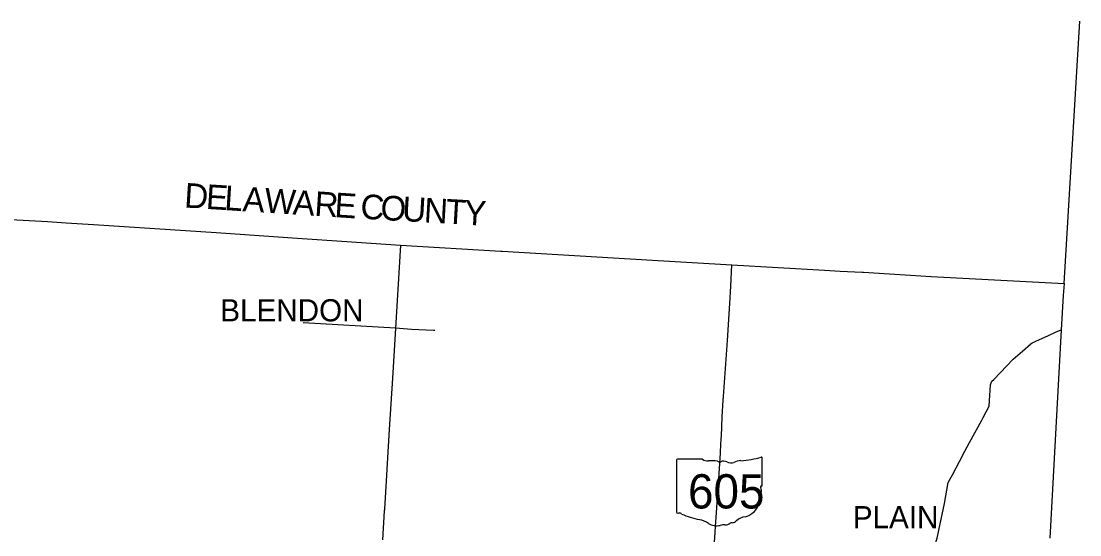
# Model space of a CAD drawing. Extents: x -1146 to -445, y -1283 to -822.
# Drawn here: x -822.8 to -715.2, y -934.9 to -882.7 of the extents above; entities that cross this region are included whole.
import ezdxf

# ---------------------------------------------------------------- set-up
doc = ezdxf.new("R2010")
doc.units = 0
for name, color, linetype in [('GM_X_Adjacent_County', 7, 'Continuous'), ('GM_X_Adjacent_County_Text', 7, 'Continuous'), ('GM_X_County', 7, 'Continuous'), ('GM_X_State_Route', 7, 'Continuous'), ('GM_X_State_Shield', 7, 'Continuous'), ('GM_X_Township', 7, 'Continuous'), ('GM_X_Township_Road', 7, 'Continuous'), ('GM_X_Township_Text', 7, 'Continuous'), ('GM_X_US_Route', 7, 'Continuous')]:
    doc.layers.add(name, color=color, linetype=linetype)

msp = doc.modelspace()

# ---------------------------------------------------------------- linework, layer by layer
at = {"layer": 'GM_X_Adjacent_County'}
msp.add_line((-716.85, -909.34), (-715.24, -882.72), dxfattribs=at)
at = {"layer": 'GM_X_County'}
msp.add_lwpolyline([(-826.99, -902.68), (-820.11, -903.07), (-818.19, -903.2), (-815.43, -903.36), (-802.96, -904.19), (-794.23, -904.79), (-790.21, -905.06), (-784.25, -905.46), (-774.05, -906.08), (-773.92, -906.08), (-758.64, -906.97), (-750.59, -907.45), (-741.19, -907.99), (-739.59, -908.09), (-737.35, -908.21), (-737.22, -908.22), (-730.34, -908.64), (-716.85, -909.34), (-716.93, -910.57), (-717.15, -914.05), (-718.3, -935.2)], dxfattribs=at)
at = {"layer": 'GM_X_State_Route'}
for points in [[(-751.65, -924.87), (-751.57, -922.88), (-751.46, -921.19), (-751.44, -920.83), (-751.04, -915.14), (-750.8, -911.37), (-750.69, -909.61), (-750.59, -907.45)], [(-751.75, -926.58), (-751.74, -926.45), (-751.66, -925.08), (-751.65, -924.87)], [(-752.28, -934.68), (-752.24, -933.98), (-752.18, -933.1), (-751.92, -929.18), (-751.85, -928.14), (-751.75, -926.58)], [(-752.34, -935.57), (-752.28, -934.68)]]:
    msp.add_lwpolyline(points, dxfattribs=at)
at = {"layer": 'GM_X_State_Shield'}
for p, q in [((-756.21, -927.29), (-756.21, -932.57)), ((-753.57, -927.2), (-756.12, -927.2)), ((-747.51, -929.83), (-747.51, -927.07)), ((-747.51, -929.83), (-747.51, -929.83))]:
    msp.add_line(p, q, dxfattribs=at)
for centre, major_axis, start_param, end_param in [((-756.11, -927.28), (0.101, 0), 1.712693, 3.28349), ((-752.97, -926.59), (0.978, 0), 4.042523, 4.731795), ((-752.64, -930.16), (3.51, 0), 1.404758, 1.657858), ((-751.84, -927.25), (0.282, 0), 3.836095, 5.185415), ((-751.43, -927.86), (0.586, 0), 0.950623, 2.079405), ((-750.67, -927.02), (0.705, 0), 4.081561, 5.145723), ((-749.43, -928.81), (1.86, 0), 1.699011, 2.107814), ((-750.6, -920), (9.23, 0), 4.814394, 5.042369), ((-747.6, -927.06), (0.0969, 0), 6.141152, 7.989035), ((-747.53, -930.03), (0.15, 0), 1.883978, 3.671073), ((-748.48, -930.38), (0.9, 0), 5.934695, 6.695948), ((-747.61, -929.84), (0.104, 0), 5.05454, 6.418171), ((-750.09, -931.34), (2.31, 0), 5.101752, 6.440018), ((-747.16, -930.99), (0.655, 0), 2.387724, 3.262537), ((-756.11, -932.58), (0.102, 0), 3.00124, 4.508301), ((-756.09, -932.04), (0.776, 0), 4.665946, 4.897461), ((-755.93, -932.88), (0.28, 0), 0.519207, 1.627899), ((-752.4, -928.13), (6.66, 0), 4.195997, 4.488961), ((-754.39, -934.95), (2.08, 0), 0.823519, 1.323587), ((-749.11, -934.06), (1.26, 0), 1.647645, 2.488434), ((-752.13, -932.9), (1.32, 0), 4.026481, 4.996735), ((-751.37, -934.73), (1.09, 0), 1.495662, 1.94098), ((-751.27, -933.3), (0.705, 0), 4.691044, 5.507374), ((-750.63, -933.81), (0.198, 0), 1.147584, 2.315152), ((-750.72, -933.08), (0.746, 0), 4.937069, 5.64225)]:
    msp.add_ellipse(centre, major_axis=major_axis, ratio=0.8, start_param=start_param, end_param=end_param, dxfattribs=at)
at = {"layer": 'GM_X_Township'}
msp.add_lwpolyline([(-784.25, -905.46), (-785.07, -918.97), (-785.41, -924.17), (-785.88, -932.27), (-785.88, -932.35), (-785.89, -932.43), (-786.07, -935.38)], dxfattribs=at)
at = {"layer": 'GM_X_Township_Road'}
msp.add_lwpolyline([(-780.77, -914.13), (-780.9, -914.13), (-783.14, -914.01), (-784.74, -913.9), (-794.14, -913.36)], dxfattribs=at)
at = {"layer": 'GM_X_US_Route'}
for points in [[(-728.18, -928.77), (-727.47, -927.43), (-726.91, -926.38), (-726.44, -925.49), (-725.21, -923.22), (-725.07, -922.95), (-724.46, -921.82), (-724.45, -921.78), (-724.37, -920.73), (-724.3, -919.66), (-724.25, -919.44), (-724.19, -919.27), (-723.99, -919.09), (-722.03, -917.05), (-721.05, -916.22), (-720.23, -915.49), (-720.08, -915.38), (-719.93, -915.3), (-719.72, -915.21), (-718.41, -914.63), (-717.72, -914.31), (-717.15, -914.05)], [(-729.57, -934.39), (-728.98, -931.71), (-728.6, -929.57), (-728.18, -928.77)], [(-730.18, -936.09), (-730.07, -935.98), (-729.96, -935.82), (-729.86, -935.65), (-729.8, -935.43), (-729.75, -935.21), (-729.57, -934.39)]]:
    msp.add_lwpolyline(points, dxfattribs=at)

# ---------------------------------------------------------------- texts
at = {"layer": 'GM_X_Adjacent_County_Text'}
for s, rotation, p in [('D', 356.3406, (-806.26, -901.63)), ('E', 356.3415, (-804.06, -901.77)), ('L', 356.3411, (-802.19, -901.89)), ('A', 356.3406, (-800.33, -902.01)), ('W', 356.3413, (-798.12, -902.15)), ('A', 356.3406, (-795.24, -902.34)), ('R', 356.3436, (-793.04, -902.48)), ('E', 356.3561, (-791, -902.61)), ('C', 356.8615, (-788.36, -902.77)), ('O', 356.7513, (-786.33, -902.89)), ('U', 356.7469, (-784.12, -903.01)), ('N', 356.7473, (-781.91, -903.14)), ('T', 356.7475, (-779.7, -903.26)), ('Y', 356.7473, (-777.84, -903.37))]:
    msp.add_text(s, height=2.5, rotation=rotation, dxfattribs=at).set_placement(p)
at = {"layer": 'GM_X_State_Shield'}
msp.add_text('605', height=3.48, dxfattribs=at).set_placement((-755.04, -932.2))
at = {"layer": 'GM_X_Township_Text'}
for s, p in [('BLENDON', (-802.55, -913.2)), ('PLAIN', (-738.3, -934.21))]:
    msp.add_text(s, height=2.25, rotation=0, dxfattribs=at).set_placement(p)

doc.saveas('drawing.dxf')
